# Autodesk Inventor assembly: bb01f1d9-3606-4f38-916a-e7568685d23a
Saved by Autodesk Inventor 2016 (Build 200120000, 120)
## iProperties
Created: 2016-09
Part Number: bb01f1d9-3606-4f38-916a-e7568685d23a
Document SubType Name: Assembly
Designer: Administrator
Author: Administrator
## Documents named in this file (15)
- c:\worker\convert-fusion-aug-2016\tmp\job-1\13\output\files\2055b865-881d-4af8-ae30-e7b46ec3c804\bb01f1d9-3606-4f38-916a-e7568685d23a.iam
- c:\worker\convert-fusion-aug-2016\tmp\job-1\13\output\files\2055b865-881d-4af8-ae30-e7b46ec3c804\board.ipt
- c:\worker\convert-fusion-aug-2016\tmp\job-1\13\output\files\2055b865-881d-4af8-ae30-e7b46ec3c804\micro_usb (1).iam
- c:\worker\convert-fusion-aug-2016\tmp\job-1\13\output\files\2055b865-881d-4af8-ae30-e7b46ec3c804\qfp16 v2.iam
- c:\worker\convert-fusion-aug-2016\tmp\job-1\13\output\files\2055b865-881d-4af8-ae30-e7b46ec3c804\tqfp64 v1.iam
- c:\worker\convert-fusion-aug-2016\tmp\job-1\13\output\files\2055b865-881d-4af8-ae30-e7b46ec3c804\qfp16 v2 (1).iam
- c:\worker\convert-fusion-aug-2016\tmp\job-1\13\output\files\2055b865-881d-4af8-ae30-e7b46ec3c804\cap0402 v2.ipt
- c:\worker\convert-fusion-aug-2016\tmp\job-1\13\output\files\2055b865-881d-4af8-ae30-e7b46ec3c804\wson-6 v3.iam
- c:\worker\convert-fusion-aug-2016\tmp\job-1\13\output\files\2055b865-881d-4af8-ae30-e7b46ec3c804\diode_0402 v1.ipt
- c:\worker\convert-fusion-aug-2016\tmp\job-1\13\output\files\2055b865-881d-4af8-ae30-e7b46ec3c804\cap0603_03 v3.ipt
- c:\worker\convert-fusion-aug-2016\tmp\job-1\13\output\files\2055b865-881d-4af8-ae30-e7b46ec3c804\cap0402 v2 (1).ipt
- c:\worker\convert-fusion-aug-2016\tmp\job-1\13\output\files\2055b865-881d-4af8-ae30-e7b46ec3c804\smt_led_0805 v2.ipt
- c:\worker\convert-fusion-aug-2016\tmp\job-1\13\output\files\2055b865-881d-4af8-ae30-e7b46ec3c804\crystal_dfn4 v8.iam
- c:\worker\convert-fusion-aug-2016\tmp\job-1\13\output\files\2055b865-881d-4af8-ae30-e7b46ec3c804\smt_tactile_button_2 v2.iam
- c:\worker\convert-fusion-aug-2016\tmp\job-1\13\output\files\2055b865-881d-4af8-ae30-e7b46ec3c804\resistor_0603 v3.ipt
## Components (27 placed, 18 different names)
1. board:1
2. micro_usb (1):1 [sub-assembly]
3. qfp16 v2:1 [sub-assembly]
4. tqfp64 v1:1 [sub-assembly]
5. qfp16 v2 (1):1 [sub-assembly]
6. cap0402 v2:1
7. wson-6 v3:1 [sub-assembly]
8. diode_0402 v1:1
9. cap0603_03 v3:1
10. cap0402 v2 (1):1
11. cap0402 v2 (1):1:1
12. diode_0402 v1:1:1
13. diode_0402 v1:2
14. smt_led_0805 v2:1
15. crystal_dfn4 v8:1 [sub-assembly]
16. cap0402 v2:1:1
17. cap0402 v2:2
18. cap0402 v2:3
19. cap0603_03 v3:1:1
20. cap0603_03 v3:2
21. cap0603_03 v3:3
22. cap0603_03 v3:4
23. diode_0402 v1:3
24. cap0402 v2:4
25. cap0402 v2:5
26. smt_tactile_button_2 v2:1 [sub-assembly]
27. resistor_0603 v3:1
